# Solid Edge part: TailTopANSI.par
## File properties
Author: harmonj5
Template: ansi part.par
Last saved by: harmonj5
Revision: 5
Application: Solid Edge
Accuracy: 0.990
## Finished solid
Body 1: solid body, 29 faces, 78 edges, 52 vertices.
  Faces by surface: plane 29
  Edges by curve: line 78
Bounding box of the edges (mm): 101.600 x 6.350 x 837.814, from (-79.0144, -6.35, -132.8944) to (22.5856, 0, 704.9197).
Planar faces by outward normal: +y 1, +z 2, -y 2, -z 2, oblique 22
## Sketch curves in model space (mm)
line (10.7392, 0, 70.2288) -> (11.0053, 0, 60.7039)
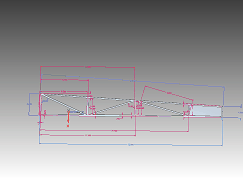
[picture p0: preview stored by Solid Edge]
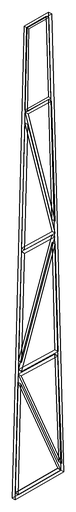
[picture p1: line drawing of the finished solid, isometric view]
